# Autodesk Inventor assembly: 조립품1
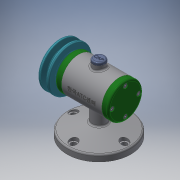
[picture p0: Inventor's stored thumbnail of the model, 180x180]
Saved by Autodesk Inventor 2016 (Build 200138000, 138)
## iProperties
Created: 2018-12
Part Number: 조립품1
Document SubType Name: Assembly
Designer: Administrator
Author: Administrator
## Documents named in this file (15)
- C:\Users\Administrator\Desktop\주재현\481208V1018\조립품1.iam
- C:\Users\Administrator\Desktop\주재현\481208V1018\부품1.ipt
- C:\Users\Administrator\Desktop\주재현\481208V1018\V벨트풀리.ipt
- C:\Users\Administrator\Desktop\주재현\481208V1018\축.ipt
- C:\Users\Administrator\Desktop\주재현\481208V1018\키 3 x 3 x 12.ipt
- C:\Users\Administrator\Desktop\주재현\481208V1018\너트 M8.ipt
- 너트 M8.ipt
- C:\Users\Administrator\Desktop\주재현\481208V1018\와셔 8x17.ipt
- C:\Users\Administrator\Desktop\주재현\481208V1018\스프링와셔 8.ipt
- C:\Users\Administrator\Desktop\주재현\481208V1018\베어링 15 x 32 x 9.ipt
- C:\Users\Administrator\Desktop\주재현\481208V1018\앞커버.ipt
- C:\Users\Administrator\Desktop\주재현\481208V1018\오일 실 15 25 7.ipt
- C:\Users\Administrator\Desktop\주재현\481208V1018\뒤커버.ipt
- C:\Users\Administrator\Desktop\주재현\481208V1018\볼트 M4 x 12.ipt
- C:\Users\Administrator\Desktop\주재현\481208V1018\고무캡.ipt
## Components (2 placed, 2 different names)
1. V벨트풀리:1
2. 고무캡:1
